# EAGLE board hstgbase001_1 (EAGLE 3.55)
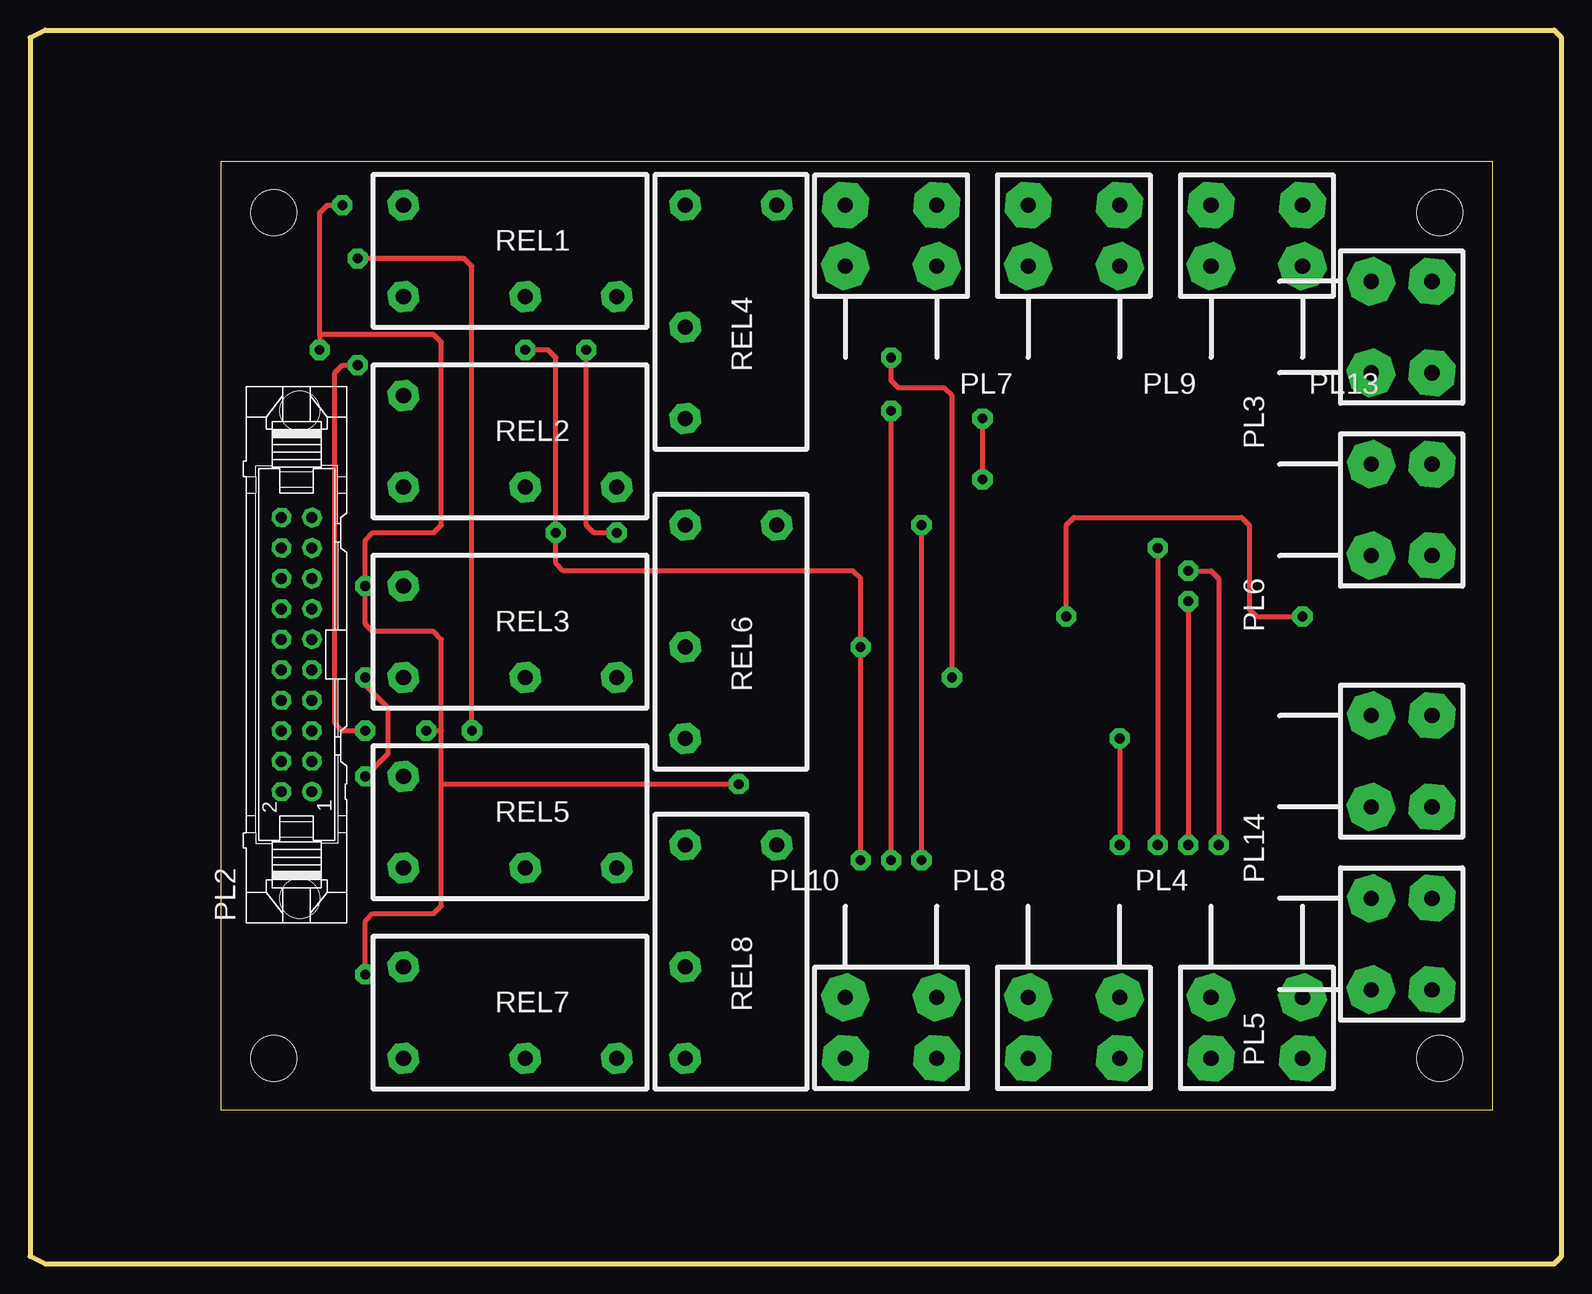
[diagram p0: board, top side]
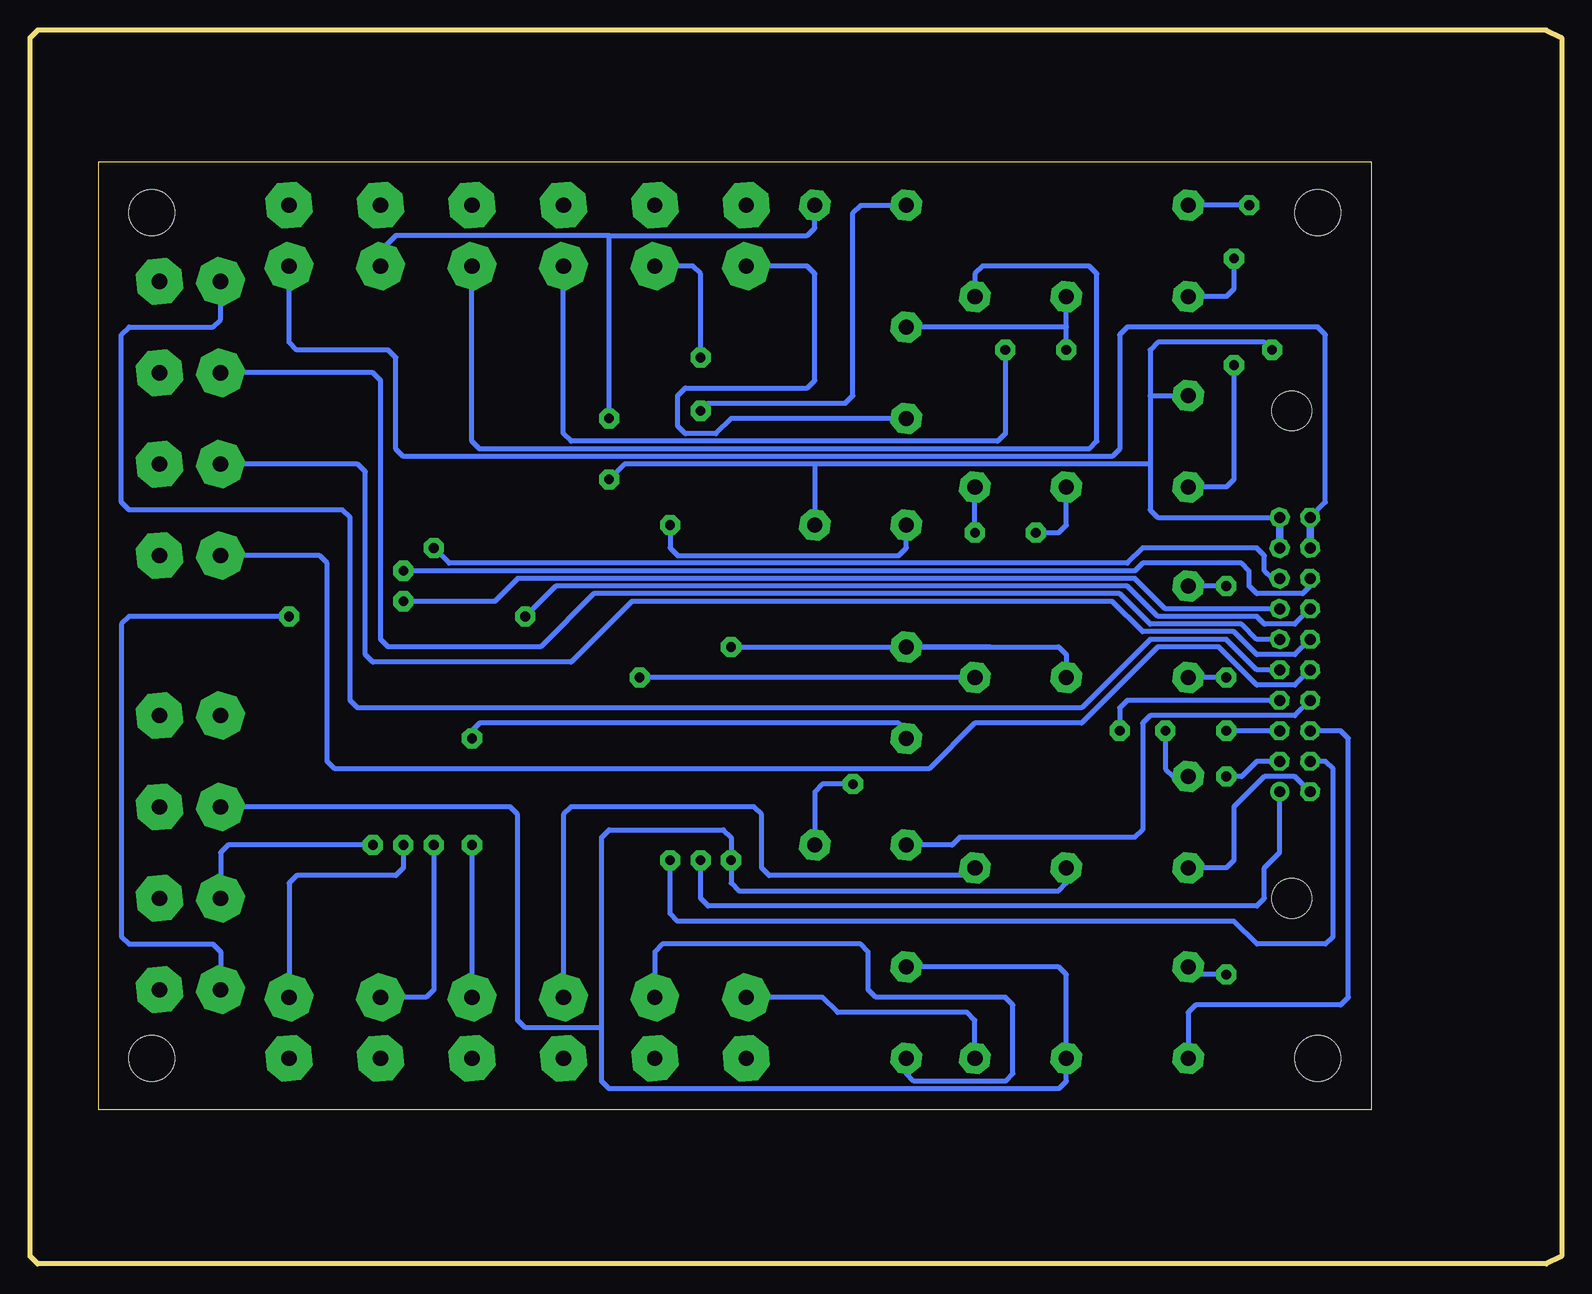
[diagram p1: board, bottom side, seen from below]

Size 127.64 x 102.87 mm. Coordinates in mm from the lower left corner, seen from the top.
Outline: 121.92,12.86 121.92,91.91 15.88,91.91 15.88,12.86 121.92,12.86
Outline: 0,0.63 1.27,0 127,0 127.64,0.63 127.64,102.23 127,102.87 1.27,102.87 0,102.23 0,0.63
Copper layers used: Top, Bottom
Holes 3.81 mm at 20.32,17.14 20.32,87.63 117.47,87.63 117.47,17.14
vRestrict: area 69.9,50.8 to 94,74.9

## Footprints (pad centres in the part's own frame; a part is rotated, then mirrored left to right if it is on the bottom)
V = drill 0.914 pad 1.6 round:  -11.43,-1.27 | drill 0.914 pad 1.6 octagon:  -11.43,1.27;  -8.89,-1.27;  -8.89,1.27;  -6.35,-1.27;  -6.35,1.27;  -3.81,-1.27;  -3.81,1.27;  -1.27,-1.27;  -1.27,1.27;  1.27,-1.27;  1.27,1.27;  3.81,-1.27;  3.81,1.27;  6.35,-1.27;  6.35,1.27;  8.89,-1.27;  8.89,1.27;  11.43,-1.27;  11.43,1.27 | hole 3.302: 20.32,-0.254; -20.32,-0.254
3MM = drill 1.27 pad 3.81 octagon:  0,0;  7.62,0;  0,-5.08;  7.62,-5.08
LAIS_R = drill 1.27 pad 2.54 octagon:  -12.7,5.08;  -12.7,-2.54;  -2.54,-2.54;  5.08,-2.54

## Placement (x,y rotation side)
PL2  20V  [V]  22.23,50.8 90 top
PL3  6_3MM  [3MM]  111.76,74.3 90 top
PL4  6_3MM  [3MM]  98.42,22.23 0 top
PL5  6_3MM  [3MM]  111.76,22.86 90 top
PL6  6_3MM  [3MM]  111.76,59.05 90 top
PL7  6_3MM  [3MM]  75.56,83.19 180 top
PL8  6_3MM  [3MM]  83.19,22.23 0 top
PL9  6_3MM  [3MM]  90.81,83.19 180 top
PL10  6_3MM  [3MM]  67.94,22.23 0 top
PL13  6_3MM  [3MM]  106.05,83.19 180 top
PL14  6_3MM  [3MM]  111.76,38.1 90 top
REL1  REL_RE  [LAIS_R]  43.81,83.19 0 top
REL2  REL_RE  [LAIS_R]  43.81,67.31 0 top
REL3  REL_RE  [LAIS_R]  43.81,51.44 0 top
REL4  REL_RE  [LAIS_R]  57.15,75.56 270 top
REL5  REL_RE  [LAIS_R]  43.81,35.56 0 top
REL6  REL_RE  [LAIS_R]  57.15,48.89 270 top
REL7  REL_RE  [LAIS_R]  43.81,19.68 0 top
REL8  REL_RE  [LAIS_R]  57.15,22.23 270 top

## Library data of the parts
PL2 = pinh-v
PL3-PL10 PL13 PL14 REL1-REL8 = andit4at

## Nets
N$1: PL14. REL1. REL2. REL3. REL4. REL5. REL6. REL7. REL8.
N$2: PL9. REL1.
N$3: PL9. REL2.
N$4: PL7. REL3.
N$9: PL2. REL6.
N$10: PL2. REL7.
N$11: PL10. REL8.
N$12: PL10. REL7.
N$13: PL8. REL6.
N$15: PL8. REL5.
N$16: PL7. REL4.
N$17: PL2. REL8.
N$18: PL2. REL5.
N$19: PL2. REL4.
N$20: PL2. REL3.
N$21: PL2. REL2.
N$22: PL2. REL1.
N$23: PL2. PL13. REL1. REL2. REL3. REL4. REL5. REL6. REL7. REL8.
N$24: PL2. PL5.
N$25: PL2. PL5.
N$26: PL2. PL4.
N$27: PL2. PL4.
N$28: PL2. PL3.
N$29: PL2. PL3.
N$31: PL2. PL13.
N$34: PL2. PL6.
N$35: PL2. PL6.

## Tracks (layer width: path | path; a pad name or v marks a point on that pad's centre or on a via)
N$1  (via drill 0.81 pad 1.68)
  Top 0.406: v41.27,76.2 43.18,76.2 43.81,75.56 v43.81,60.96 43.81,58.42 44.45,57.78 68.58,57.78 69.22,57.15 v69.22,51.44 v69.22,33.66
  Bottom 0.406: 111.76,38.1 87.63,38.1 87,37.47 87,20.32 86.36,19.68 80.01,19.68 | 80.01,19.68 80.01,35.56 79.38,36.2 69.85,36.2 69.22,35.56 v69.22,33.66 69.22,31.75 68.58,31.11 41.91,31.11 41.27,31.75 41.27,33.02 | 41.27,15.24 41.27,17.14 | 80.01,19.68 80.01,15.24 79.38,14.6 41.91,14.6 41.27,15.24 | 41.27,15.24 41.27,24.13 41.91,24.77 54.61,24.77 | 41.27,78.11 54.61,78.11 | 41.27,78.11 41.27,80.64 | 47.62,51.44 54.61,51.44 | v41.27,76.2 41.27,78.11 | 41.27,64.77 41.27,61.59 41.91,60.96 v43.81,60.96 | 41.27,48.89 41.27,50.8 41.91,51.44 47.62,51.44 | v69.22,51.44 47.62,51.44
N$2
  Bottom 0.406: 90.81,83.19 90.81,68.58 90.17,67.94 39.37,67.94 38.73,68.58 38.73,82.55 39.37,83.19 48.26,83.19 48.9,82.55 REL1.
N$3  (via drill 0.81 pad 1.68)
  Top 0.406: v46.36,76.2 46.36,61.59 46.99,60.96 v48.9,60.96
  Bottom 0.406: 83.19,83.19 83.19,69.22 82.55,68.58 46.99,68.58 46.36,69.22 v46.36,76.2 | v48.9,60.96 REL2.
N$4  (via drill 0.81 pad 1.68)
  Top 0.406: v76.84,48.89 76.84,72.39 76.2,73.03 72.39,73.03 71.75,73.66 v71.75,75.56
  Bottom 0.406: 75.56,83.19 72.39,83.19 71.75,82.55 v71.75,75.56 | REL3. v76.84,48.89
N$9  (via drill 0.81 pad 1.68)
  Top 0.406: v74.3,33.66 v74.3,61.59
  Bottom 0.406: 20.95,41.91 19.68,41.91 19.05,41.27 19.05,27.3 19.68,26.67 25.4,26.67 27.3,28.57 73.66,28.57 74.3,29.21 v74.3,33.66 | 54.61,61.59 54.61,59.69 55.24,59.05 73.66,59.05 74.3,59.69 v74.3,61.59
N$10
  Bottom 0.406: 20.95,44.45 18.41,44.45 17.78,43.81 17.78,22.23 18.41,21.59 30.48,21.59 31.12,20.95 31.12,17.14
N$11
  Bottom 0.406: 75.56,22.23 75.56,26.04 74.93,26.67 58.42,26.67 57.78,26.04 57.78,22.86 57.15,22.23 46.36,22.23 45.72,21.59 45.72,15.88 46.36,15.24 53.98,15.24 54.61,15.88 REL8.
N$12
  Bottom 0.406: 67.94,22.23 61.59,22.23 60.33,20.95 49.53,20.95 48.9,20.32 REL7.
N$13  (via drill 0.81 pad 1.68)
  Top 0.406: v90.81,43.81 v90.81,34.92
  Bottom 0.406: v90.81,34.92 90.81,22.23 | REL6. 54.61,44.45 55.24,45.08 90.17,45.08 90.81,44.45 v90.81,43.81
N$15
  Bottom 0.406: 83.19,22.23 83.19,37.47 82.55,38.1 67.31,38.1 66.67,37.47 66.67,33.02 66.04,32.38 49.53,32.38 REL5.
N$16
  Bottom 0.406: 67.94,83.19 62.87,83.19 62.23,82.55 62.23,73.66 62.87,73.03 73.03,73.03 73.66,72.39 73.66,69.85 73.03,69.22 70.48,69.22 69.22,70.48 REL4.
N$17
  Bottom 0.406: 20.95,46.99 22.23,45.72 34.29,45.72 34.92,45.08 34.92,36.2 35.56,35.56 50.16,35.56 50.8,34.92 54.61,34.92
N$18
  Bottom 0.406: 20.95,39.37 22.23,40.64 24.77,40.64 27.3,38.1 27.3,33.66 27.94,33.02 31.12,33.02
N$19  (via drill 0.81 pad 1.68)
  Top 0.406: v71.75,33.66 v71.75,71.12
  Bottom 0.406: 23.5,39.37 23.5,34.29 24.77,33.02 24.77,30.48 25.4,29.84 71.12,29.84 71.75,30.48 v71.75,33.66 | v71.75,71.12 71.12,71.75 59.69,71.75 59.05,72.39 59.05,87.63 58.42,88.27 54.61,88.27
N$20  (via drill 0.81 pad 1.68)
  Top 0.406: v27.94,40.64 29.84,42.55 29.84,46.36 27.94,48.26 v27.94,48.89
  Bottom 0.406: 23.5,41.91 25.4,41.91 26.67,40.64 v27.94,40.64 | v27.94,48.89 31.12,48.89
N$21  (via drill 0.81 pad 1.68)
  Top 0.406: v27.3,74.93 26.04,74.93 25.4,74.3 25.4,45.08 26.04,44.45 v27.94,44.45
  Bottom 0.406: 23.5,44.45 v27.94,44.45 | v27.3,74.93 27.3,65.41 27.94,64.77 31.12,64.77
N$22  (via drill 0.81 pad 1.68)
  Top 0.406: v36.83,44.45 36.83,83.19 36.2,83.82 v27.3,83.82
  Bottom 0.406: 23.5,46.99 36.2,46.99 36.83,46.36 v36.83,44.45 | 31.12,80.64 27.94,80.64 27.3,81.28 v27.3,83.82
N$23  (via drill 0.81 pad 1.68)
  Top 0.406: v79.38,65.41 v79.38,70.48 | v26.04,88.27 24.77,88.27 24.13,87.63 24.13,77.47 | 34.29,40 34.29,44.45 | 34.29,44.45 v33.02,44.45 | 34.29,44.45 34.29,52.07 33.66,52.7 28.57,52.7 27.94,53.34 v27.94,56.52 27.94,60.33 28.57,60.96 33.66,60.96 34.29,61.59 34.29,76.84 33.66,77.47 24.13,77.47 | 24.13,77.47 v24.13,76.2 | v27.94,24.13 27.94,28.57 28.57,29.21 33.66,29.21 34.29,29.84 34.29,40 | 34.29,40 v59.05,40
  Bottom 0.406: 23.5,59.69 23.5,62.23 33.66,62.23 34.29,62.86 34.29,66.67 | 98.42,83.19 98.42,84.45 97.16,85.73 79.38,85.73 | v79.38,70.48 79.38,85.73 | 34.29,66.67 62.23,66.67 | v79.38,65.41 78.1,66.67 62.23,66.67 | v26.04,88.27 31.12,88.27 | 79.38,85.73 62.87,85.73 62.23,86.36 62.23,88.27 | 62.23,66.67 62.23,61.59 | 34.29,72.39 34.29,66.67 | 34.29,72.39 31.12,72.39 | 34.29,72.39 34.29,76.2 33.66,76.84 24.77,76.84 v24.13,76.2 | v33.02,44.45 33.02,41.27 32.39,40.64 31.12,40.64 | v59.05,40 61.59,40 62.23,39.37 62.23,34.92 | v27.94,56.52 31.12,56.52 | 31.12,24.77 30.48,24.13 v27.94,24.13
  Bottom 0.61: 23.5,62.23 23.5,59.69
N$24  (via drill 0.81 pad 1.68)
  Top 0.406: v106.05,53.97 102.23,53.97 101.6,54.61 101.6,61.59 100.97,62.23 87,62.23 86.36,61.59 v86.36,53.97
  Bottom 0.406: 20.95,54.61 22.23,53.34 24.77,53.34 25.4,53.97 33.66,53.97 36.2,56.52 83.82,56.52 v86.36,53.97 | 111.76,22.86 111.76,26.04 112.39,26.67 119.38,26.67 120.02,27.3 120.02,53.34 119.38,53.97 v106.05,53.97
N$25  (via drill 0.81 pad 1.68)
  Top 0.406: v99.06,34.92 99.06,57.15 98.42,57.78 v96.52,57.78
  Bottom 0.406: 20.95,57.15 20.95,56.52 21.59,55.88 25.4,55.88 26.04,56.52 26.04,57.78 26.67,58.42 34.92,58.42 35.56,57.78 v96.52,57.78 | 111.76,30.48 111.76,34.29 111.12,34.92 v99.06,34.92
N$26  (via drill 0.81 pad 1.68)
  Top 0.406: v93.98,59.69 v93.98,34.92
  Bottom 0.406: 23.5,57.15 24.13,57.15 24.77,57.78 24.77,59.05 25.4,59.69 34.92,59.69 36.2,58.42 92.71,58.42 v93.98,59.69 | 98.42,22.23 94.61,22.23 93.98,22.86 v93.98,34.92
N$27  (via drill 0.81 pad 1.68)
  Top 0.406: v96.52,55.25 v96.52,34.92
  Bottom 0.406: 23.5,54.61 33.02,54.61 35.56,57.15 87,57.15 88.9,55.25 v96.52,55.25 | 106.05,22.23 106.05,31.75 105.41,32.38 97.16,32.38 96.52,33.02 v96.52,34.92
N$28
  Bottom 0.406: 23.5,52.07 25.4,52.07 26.67,53.34 34.29,53.34 36.83,55.88 80.64,55.88 85.09,51.44 97.79,51.44 98.42,52.07 98.42,73.66 99.06,74.3 111.76,74.3
N$29
  Bottom 0.406: 23.5,49.53 25.4,49.53 27.94,52.07 34.29,52.07 40,46.36 100.33,46.36 100.97,46.99 100.97,62.23 101.6,62.86 119.38,62.86 120.02,63.5 120.02,77.47 119.38,78.11 112.39,78.11 111.76,78.74 111.76,81.92 111.76,82.55
N$31
  Bottom 0.406: PL2. 19.68,63.5 19.68,77.47 20.32,78.11 36.2,78.11 36.83,77.47 36.83,67.94 37.47,67.31 96.52,67.31 97.16,67.94 97.16,75.56 97.79,76.2 105.41,76.2 106.05,76.84 106.05,83.19
  Bottom 0.61: 20.95,59.69 PL2.
N$34
  Bottom 0.406: 20.95,52.07 22.23,50.8 25.4,50.8 27.3,52.7 34.92,52.7 37.47,55.25 77.47,55.25 82.55,50.17 99.06,50.17 99.69,50.8 99.69,66.04 100.33,66.67 111.76,66.67
N$35
  Bottom 0.406: 20.95,49.53 22.23,48.26 25.4,48.26 28.57,51.44 33.66,51.44 40,45.08 48.9,45.08 52.7,41.27 102.23,41.27 102.87,41.91 102.87,58.42 103.5,59.05 111.76,59.05

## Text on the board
massetop: HSTG | Base | V1_1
